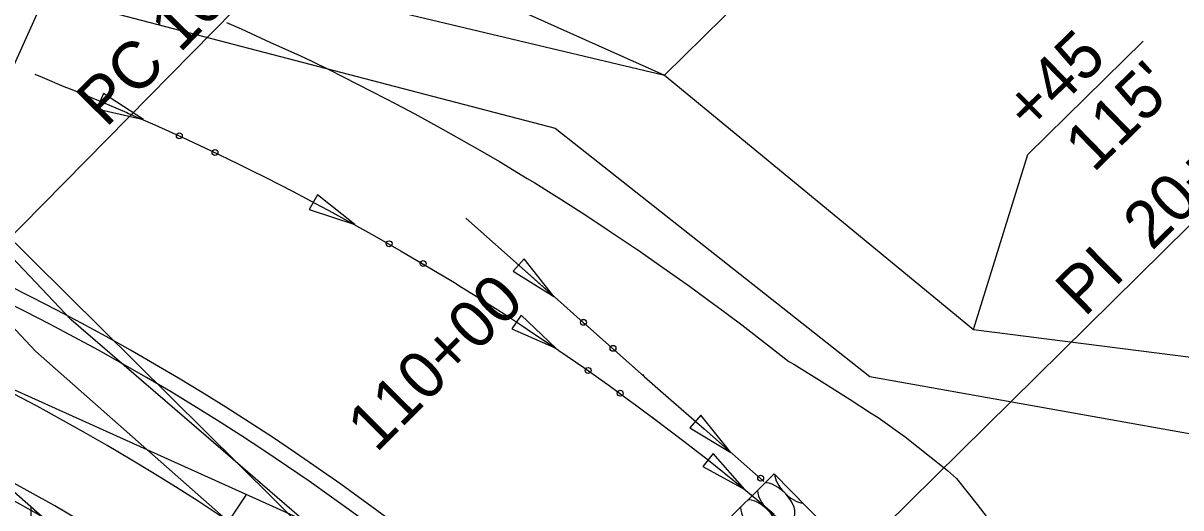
# Model space of a CAD drawing. Extents: x 1660112 to 1662239, y 668919 to 671377.
# Drawn here: x 1661235.6 to 1661383, y 670311.9 to 670373.6 of the extents above; entities that cross this region are included whole.
import ezdxf

# ---------------------------------------------------------------- set-up
doc = ezdxf.new("R2010")
doc.units = 0
for name, color, linetype in [('R_Axis', 7, 'Continuous'), ('R_Horz Alg', 7, 'Continuous'), ('R_Horz Alg Annot', 7, 'Continuous'), ('R_Proposed Const Limits_Cut', 7, 'Continuous'), ('R_Proposed Const Limits_Hand', 7, 'Continuous'), ('R_Proposed Road_Lane', 7, 'Continuous'), ('R_Proposed Road_Shoulder', 7, 'Continuous'), ('R_ROW', 7, 'Continuous'), ('R_ROW Annot', 7, 'Continuous'), ('R_TCE', 7, 'Continuous'), ('R_Water', 7, 'Continuous'), ('R_Water Annot', 7, 'Continuous'), ('S_DITCHLINE', 7, 'Continuous'), ('S_EXIST_ROW', 7, 'Continuous')]:
    doc.layers.add(name, color=color, linetype=linetype)

msp = doc.modelspace()

# ---------------------------------------------------------------- linework, layer by layer
at = {"layer": 'R_Axis'}
msp.add_line((1661236.63, 670293.2), (1661236.63, 670312.05), dxfattribs=at)
msp.add_lwpolyline([(1661157.58, 670355.45), (1661171.41, 670369.49), (1661246.63, 670303.25), (1661225.47, 670281.99)], close=True, dxfattribs=at)
at = {"layer": 'R_Horz Alg'}
for centre, radius, start, end in [((1661098.46, 670065.94), 293.82, 23.4717, 65.7806), ((1655846.99, 664877.91), 7639.44, 42.561815, 45.430038)]:
    msp.add_arc(centre, radius, start, end, dxfattribs=at)
at = {"layer": 'R_Horz Alg Annot'}
for q in [(1661239.73, 670380.01), (1661322.68, 670287.26)]:
    msp.add_line((1661218.99, 670333.9), q, dxfattribs=at)
for points in [[(1661292.41, 670405.69), (1661208.2, 670320.2)], [(1661322.68, 670287.26), (1661409.79, 670373.24)], [(1661263.98, 670313.53), (1661259.53, 670306.88)]]:
    msp.add_lwpolyline(points, dxfattribs=at)
at = {"layer": 'R_Proposed Const Limits_Cut'}
for points in [[(1661171.41, 670369.49), (1661191.23, 670389.52), (1661303.34, 670360.22), (1661343.39, 670328.65)], [(1661343.39, 670328.65), (1661484.18, 670303.54), (1661489.92, 670283.53), (1661399.85, 670249.44)]]:
    msp.add_lwpolyline(points, dxfattribs=at)
at = {"layer": 'R_Proposed Const Limits_Hand'}
msp.add_lwpolyline([(1661261.5, 670373.69), (1661263.36, 670372.86), (1661267.09, 670371.16), (1661270.85, 670369.5), (1661272.35, 670368.78), (1661274.53, 670367.7), (1661278.2, 670365.85), (1661281.85, 670363.96), (1661282.99, 670363.39), (1661285.49, 670362.05), (1661289.1, 670360.06), (1661292.68, 670358.04), (1661293.45, 670357.6), (1661296.27, 670356), (1661299.79, 670353.85), (1661300.76, 670353.26), (1661303.3, 670351.69), (1661303.71, 670351.43), (1661306.78, 670349.46), (1661308.79, 670348.15), (1661310.23, 670347.19), (1661313.66, 670344.87), (1661313.73, 670344.82), (1661317.06, 670342.51), (1661320.43, 670340.11), (1661323.52, 670337.86), (1661323.78, 670337.67), (1661327.1, 670335.19), (1661330.39, 670332.67), (1661333.1, 670330.55), (1661333.73, 670330.19), (1661337.31, 670327.96), (1661340.88, 670325.7), (1661343.49, 670324.02), (1661344.45, 670323.4), (1661347.88, 670320.95), (1661351.19, 670318.34), (1661352.85, 670317.02), (1661353.27, 670316.65), (1661354.42, 670315.64), (1661357.05, 670312.36), (1661359.61, 670309.02)], dxfattribs=at)
at = {"layer": 'R_Proposed Road_Lane'}
for radius, start, end in [(303.82, 23.4717, 65.7806), (283.82, 24.6629, 65.2815)]:
    msp.add_arc((1661098.46, 670065.94), radius, start, end, dxfattribs=at)
at = {"layer": 'R_Proposed Road_Shoulder'}
for radius, start, end in [(305.82, 23.4717, 65.7806), (281.82, 25.8293, 64.1706)]:
    msp.add_arc((1661098.46, 670065.94), radius, start, end, dxfattribs=at)
at = {"layer": 'R_ROW'}
msp.add_lwpolyline([(1661180, 670399.59), (1661317.24, 670367), (1661356.6, 670334.6), (1661492.29, 670317.34)], dxfattribs=at)
at = {"layer": 'R_ROW Annot'}
msp.add_line((1661317.24, 670367), (1661346.54, 670395.85), dxfattribs=at)
msp.add_lwpolyline([(1661356.6, 670334.6), (1661363.53, 670356.87), (1661378.18, 670371.29)], dxfattribs=at)
at = {"layer": 'R_TCE'}
msp.add_line((1661126.68, 670452.33), (1661317.24, 670367), dxfattribs=at)
at = {"layer": 'R_Water'}
for p, q in [((1661245.83, 670364.64), (1661245, 670362.69)), ((1661245.83, 670364.64), (1661245, 670362.69)), ((1661250.93, 670361.32), (1661245.83, 670364.64)), ((1661250.93, 670361.32), (1661245.83, 670364.64)), ((1661245, 670362.69), (1661250.93, 670361.32)), ((1661245, 670362.69), (1661250.93, 670361.32)), ((1661273.07, 670351.76), (1661272.05, 670349.9)), ((1661273.07, 670351.76), (1661272.05, 670349.9)), ((1661277.83, 670347.96), (1661273.07, 670351.76)), ((1661277.83, 670347.96), (1661273.07, 670351.76)), ((1661272.05, 670349.9), (1661277.83, 670347.96)), ((1661272.05, 670349.9), (1661277.83, 670347.96)), ((1661299.39, 670343.6), (1661297.99, 670342.02)), ((1661303.17, 670338.83), (1661299.39, 670343.6)), ((1661297.99, 670342.02), (1661303.17, 670338.83)), ((1661299.02, 670336.46), (1661297.84, 670334.7)), ((1661299.02, 670336.46), (1661297.84, 670334.7)), ((1661303.41, 670332.23), (1661299.02, 670336.46)), ((1661303.41, 670332.23), (1661299.02, 670336.46)), ((1661297.84, 670334.7), (1661303.41, 670332.23)), ((1661297.84, 670334.7), (1661303.41, 670332.23)), ((1661321.89, 670323.72), (1661320.5, 670322.12)), ((1661325.71, 670318.97), (1661321.89, 670323.72)), ((1661320.5, 670322.12), (1661325.71, 670318.97)), ((1661323.45, 670318.84), (1661322.12, 670317.19)), ((1661323.45, 670318.84), (1661322.12, 670317.19)), ((1661327.47, 670314.27), (1661323.45, 670318.84)), ((1661327.47, 670314.27), (1661323.45, 670318.84)), ((1661322.12, 670317.19), (1661327.47, 670314.27)), ((1661322.12, 670317.19), (1661327.47, 670314.27))]:
    msp.add_line(p, q, dxfattribs=at)
for points in [[(1661237.1, 670367.13), (1661238.03, 670366.74), (1661240.8, 670365.56), (1661241.61, 670365.23), (1661243.77, 670364.35), (1661245.22, 670363.75), (1661248.8, 670362.22), (1661249.03, 670362.12), (1661252.38, 670360.65), (1661254.17, 670359.85), (1661255.94, 670359.04), (1661259.48, 670357.38), (1661263, 670355.68), (1661264.43, 670354.98), (1661266.5, 670353.94), (1661269.99, 670352.16), (1661273.46, 670350.33), (1661274.53, 670349.76), (1661276.91, 670348.46), (1661280.34, 670346.55), (1661283.75, 670344.6), (1661284.47, 670344.18), (1661287.14, 670342.61), (1661290.51, 670340.58), (1661291.43, 670340.01), (1661293.85, 670338.5), (1661294.24, 670338.25), (1661297.17, 670336.38), (1661299.08, 670335.12), (1661300.46, 670334.21), (1661303.73, 670332.01), (1661303.8, 670331.96), (1661306.98, 670329.77), (1661310.2, 670327.48), (1661313.16, 670325.34), (1661313.4, 670325.16), (1661316.58, 670322.8), (1661319.72, 670320.4), (1661322.31, 670318.39), (1661322.85, 670317.97), (1661325.94, 670315.49), (1661329.01, 670312.98), (1661331.24, 670311.11)], [(1661237.1, 670367.13), (1661238.03, 670366.74), (1661240.8, 670365.56), (1661241.61, 670365.23), (1661243.77, 670364.35), (1661245.22, 670363.75), (1661248.8, 670362.22), (1661249.03, 670362.12), (1661250.92, 670361.29)], [(1661237.1, 670367.13), (1661238.03, 670366.74), (1661240.8, 670365.56), (1661241.61, 670365.23), (1661243.77, 670364.35), (1661245.22, 670363.75), (1661248.8, 670362.22), (1661249.03, 670362.12), (1661250.92, 670361.29)], [(1661264.51, 670354.94), (1661264.54, 670354.92)], [(1661264.51, 670354.94), (1661264.54, 670354.92)], [(1661264.54, 670354.92), (1661266.5, 670353.94), (1661269.99, 670352.16), (1661273.46, 670350.33), (1661274.53, 670349.76), (1661276.91, 670348.46), (1661277.83, 670347.95)], [(1661264.54, 670354.92), (1661266.5, 670353.94), (1661269.99, 670352.16), (1661273.46, 670350.33), (1661274.53, 670349.76), (1661276.91, 670348.46), (1661277.83, 670347.95)], [(1661291.96, 670348.79), (1661299.53, 670342.07), (1661303.63, 670338.42), (1661306.91, 670335.51), (1661307.1, 670335.35), (1661314.69, 670328.65), (1661317.45, 670326.21), (1661322.29, 670321.96), (1661329.92, 670315.29)], [(1661291.96, 670348.79), (1661299.53, 670342.07), (1661303.17, 670338.83)], [(1661290.79, 670340.4), (1661290.82, 670340.38)], [(1661290.79, 670340.4), (1661290.82, 670340.38)], [(1661290.82, 670340.38), (1661291.43, 670340.01), (1661293.85, 670338.5), (1661294.24, 670338.25), (1661297.17, 670336.38), (1661299.08, 670335.12), (1661300.46, 670334.21), (1661303.41, 670332.23)], [(1661290.82, 670340.38), (1661291.43, 670340.01), (1661293.85, 670338.5), (1661294.24, 670338.25), (1661297.17, 670336.38), (1661299.08, 670335.12), (1661300.46, 670334.21), (1661303.41, 670332.23)], [(1661314.41, 670328.89), (1661314.44, 670328.87)], [(1661314.44, 670328.87), (1661314.69, 670328.65), (1661317.45, 670326.21), (1661322.29, 670321.96), (1661325.71, 670318.97)], [(1661315.62, 670323.52), (1661315.65, 670323.5)], [(1661315.62, 670323.52), (1661315.65, 670323.5)], [(1661315.65, 670323.5), (1661316.58, 670322.8), (1661319.72, 670320.4), (1661322.31, 670318.39), (1661322.85, 670317.97), (1661325.94, 670315.49), (1661327.45, 670314.25)], [(1661315.65, 670323.5), (1661316.58, 670322.8), (1661319.72, 670320.4), (1661322.31, 670318.39), (1661322.85, 670317.97), (1661325.94, 670315.49), (1661327.45, 670314.25)]]:
    msp.add_lwpolyline(points, dxfattribs=at)
for centre in [(1661255.5, 670359.27), (1661255.5, 670359.27), (1661260.04, 670357.15), (1661260.04, 670357.15), (1661282.21, 670345.53), (1661282.21, 670345.53), (1661286.54, 670343.01), (1661286.54, 670343.01), (1661306.94, 670335.53), (1661310.7, 670332.22), (1661307.54, 670329.41), (1661307.54, 670329.41), (1661311.62, 670326.5), (1661311.62, 670326.5), (1661329.5, 670315.7)]:
    msp.add_circle(centre, 0.375, dxfattribs=at)
at = {"layer": 'R_Water Annot'}
msp.add_lwpolyline([(1661324.14, 670309.19), (1661324.68, 670308.81), (1661313.92, 670293.64), (1661360.78, 670246.19), (1661389.25, 670243.51), (1661389.18, 670242.85), (1661396.37, 670249.8), (1661331.24, 670316.23)], close=True, dxfattribs=at)
msp.add_lwpolyline([(1661385.1, 670261.3), (1661331.24, 670316.23), (1661324.14, 670309.19), (1661324.68, 670308.81), (1661313.92, 670293.64), (1661360.78, 670246.19), (1661389.25, 670243.51), (1661389.18, 670242.85), (1661390.85, 670244.46)], dxfattribs=at)
msp.add_lwpolyline([(1661385.1, 670261.3), (1661331.24, 670316.23), (1661324.14, 670309.19), (1661324.68, 670308.81), (1661313.92, 670293.64), (1661360.78, 670246.19), (1661389.25, 670243.51), (1661389.18, 670242.85), (1661390.85, 670244.46)], dxfattribs=at)
for centre, start_param, end_param in [((1661331.49, 670312.73), 3.617337, 8.876575), ((1661331.49, 670312.73), 3.617337, 8.876575), ((1661331.49, 670312.73), 2.59339, 2.661561), ((1661331.49, 670312.73), 2.59339, 2.661561), ((1661333.65, 670314.89), 3.657643, 5.728254), ((1661333.65, 670314.89), 3.657643, 5.728254), ((1661329.32, 670310.56), 3.607926, 8.769377), ((1661329.32, 670310.56), 3.607926, 8.769377), ((1661329.32, 670310.56), 2.486192, 2.670972), ((1661329.32, 670310.56), 2.486192, 2.670972)]:
    msp.add_ellipse(centre, major_axis=(2.12, -2.12), ratio=0.51, start_param=start_param, end_param=end_param, dxfattribs=at)
at = {"layer": 'S_DITCHLINE'}
for points in [[(1661299.45, 670280.74), (1661284.47, 670292.7), (1661279.2, 670294.55), (1661276.17, 670300.4), (1661276.07, 670306.25), (1661258.9, 670321.05), (1661241.72, 670335.84), (1661231.17, 670346.95), (1661220.61, 670358.06), (1661210.06, 670369.17), (1661199.5, 670380.28), (1661190.45, 670390.39), (1661181.41, 670400.5), (1661172.36, 670410.61), (1661163.31, 670420.71), (1661149.32, 670433.4), (1661135.33, 670446.1), (1661121.34, 670458.79), (1661107.35, 670471.48)], [(1661292.16, 670275.66), (1661274.83, 670292.21), (1661270.79, 670300.84), (1661264.75, 670307.54), (1661250.97, 670319.7), (1661237.18, 670331.85), (1661227.07, 670342.64), (1661216.95, 670353.42), (1661206.84, 670364.21), (1661196.72, 670375), (1661186.88, 670384.5), (1661177.03, 670394.01), (1661167.19, 670403.51), (1661157.34, 670413.01), (1661144.39, 670427.16), (1661131.45, 670441.31), (1661118.5, 670455.46), (1661105.55, 670469.61)]]:
    msp.add_lwpolyline(points, dxfattribs=at)
at = {"layer": 'S_EXIST_ROW'}
msp.add_line((1661404.92, 670177.11), (1660401.45, 671169.67), dxfattribs=at)

# ---------------------------------------------------------------- texts
at = {"layer": 'R_Horz Alg Annot'}
for s, rotation, p in [('PC 109+50.80', 45.43, (1661246.18, 670360.19)), ('PI  20+64.75', 44.6261, (1661370.73, 670336.09)), ('110+00', 45.061, (1661280.58, 670318.83))]:
    msp.add_text(s, height=6, rotation=rotation, dxfattribs=at).set_placement(p)
at = {"layer": 'R_ROW Annot'}
for s, p in [('+45', (1661364.02, 670359.4)), ("115'", (1661371.87, 670354.48))]:
    msp.add_text(s, height=6, rotation=44.328, dxfattribs=at).set_placement(p)

doc.saveas('drawing.dxf')
